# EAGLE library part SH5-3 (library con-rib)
RIBBON CABLE CONNECTOR Flachstecker / Faston
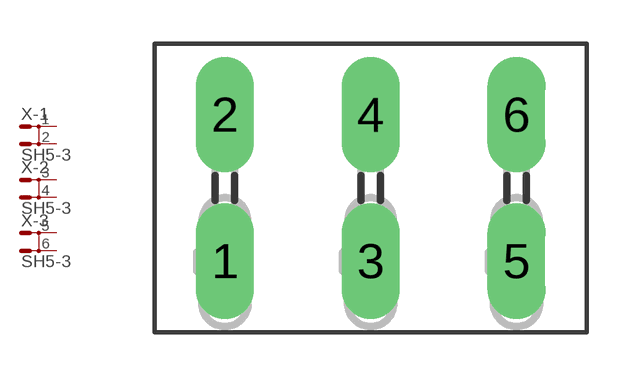
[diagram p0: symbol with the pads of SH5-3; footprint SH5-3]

Designator prefix X; gates -1=MD -2=MD -3=MD

## SH5-3  [SH5-3]
1  -1:1  pas
2  -1:2  pas
3  -2:1  pas
4  -2:2  pas
5  -3:1  pas
6  -3:2  pas

## Footprint SH5-3 (pad centres in mm)
RIBBON CABLE CONNECTOR Flachstecker / Faston
drill 1.321 long: 1 -5.004,-2.515; 2 -5.004,2.515; 3 0,-2.515; 4 0,2.515; 5 5.004,-2.515; 6 5.004,2.515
